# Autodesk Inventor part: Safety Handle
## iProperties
Shininess: 77.0
Length Units: 11269
Angle Units: 11279
Time Units: 11290
Mass Units: 11283
Length Display Precision: 3
Angle Display Precision: 2
Created: 2002-02
Part Number: Safety Handle
Document SubType Name: Modeling
Designer: ***
Density: 1 g/cm^3
Density: 0.0
Volumn: 0.0
Area: 0.0
PropertySet Name: Model Information
Control State: 0
Master: False
Checked Out: False
Author: ***
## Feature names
1. Revolution1
2. Revolution2
